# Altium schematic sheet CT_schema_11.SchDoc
size 387 x 385 mm
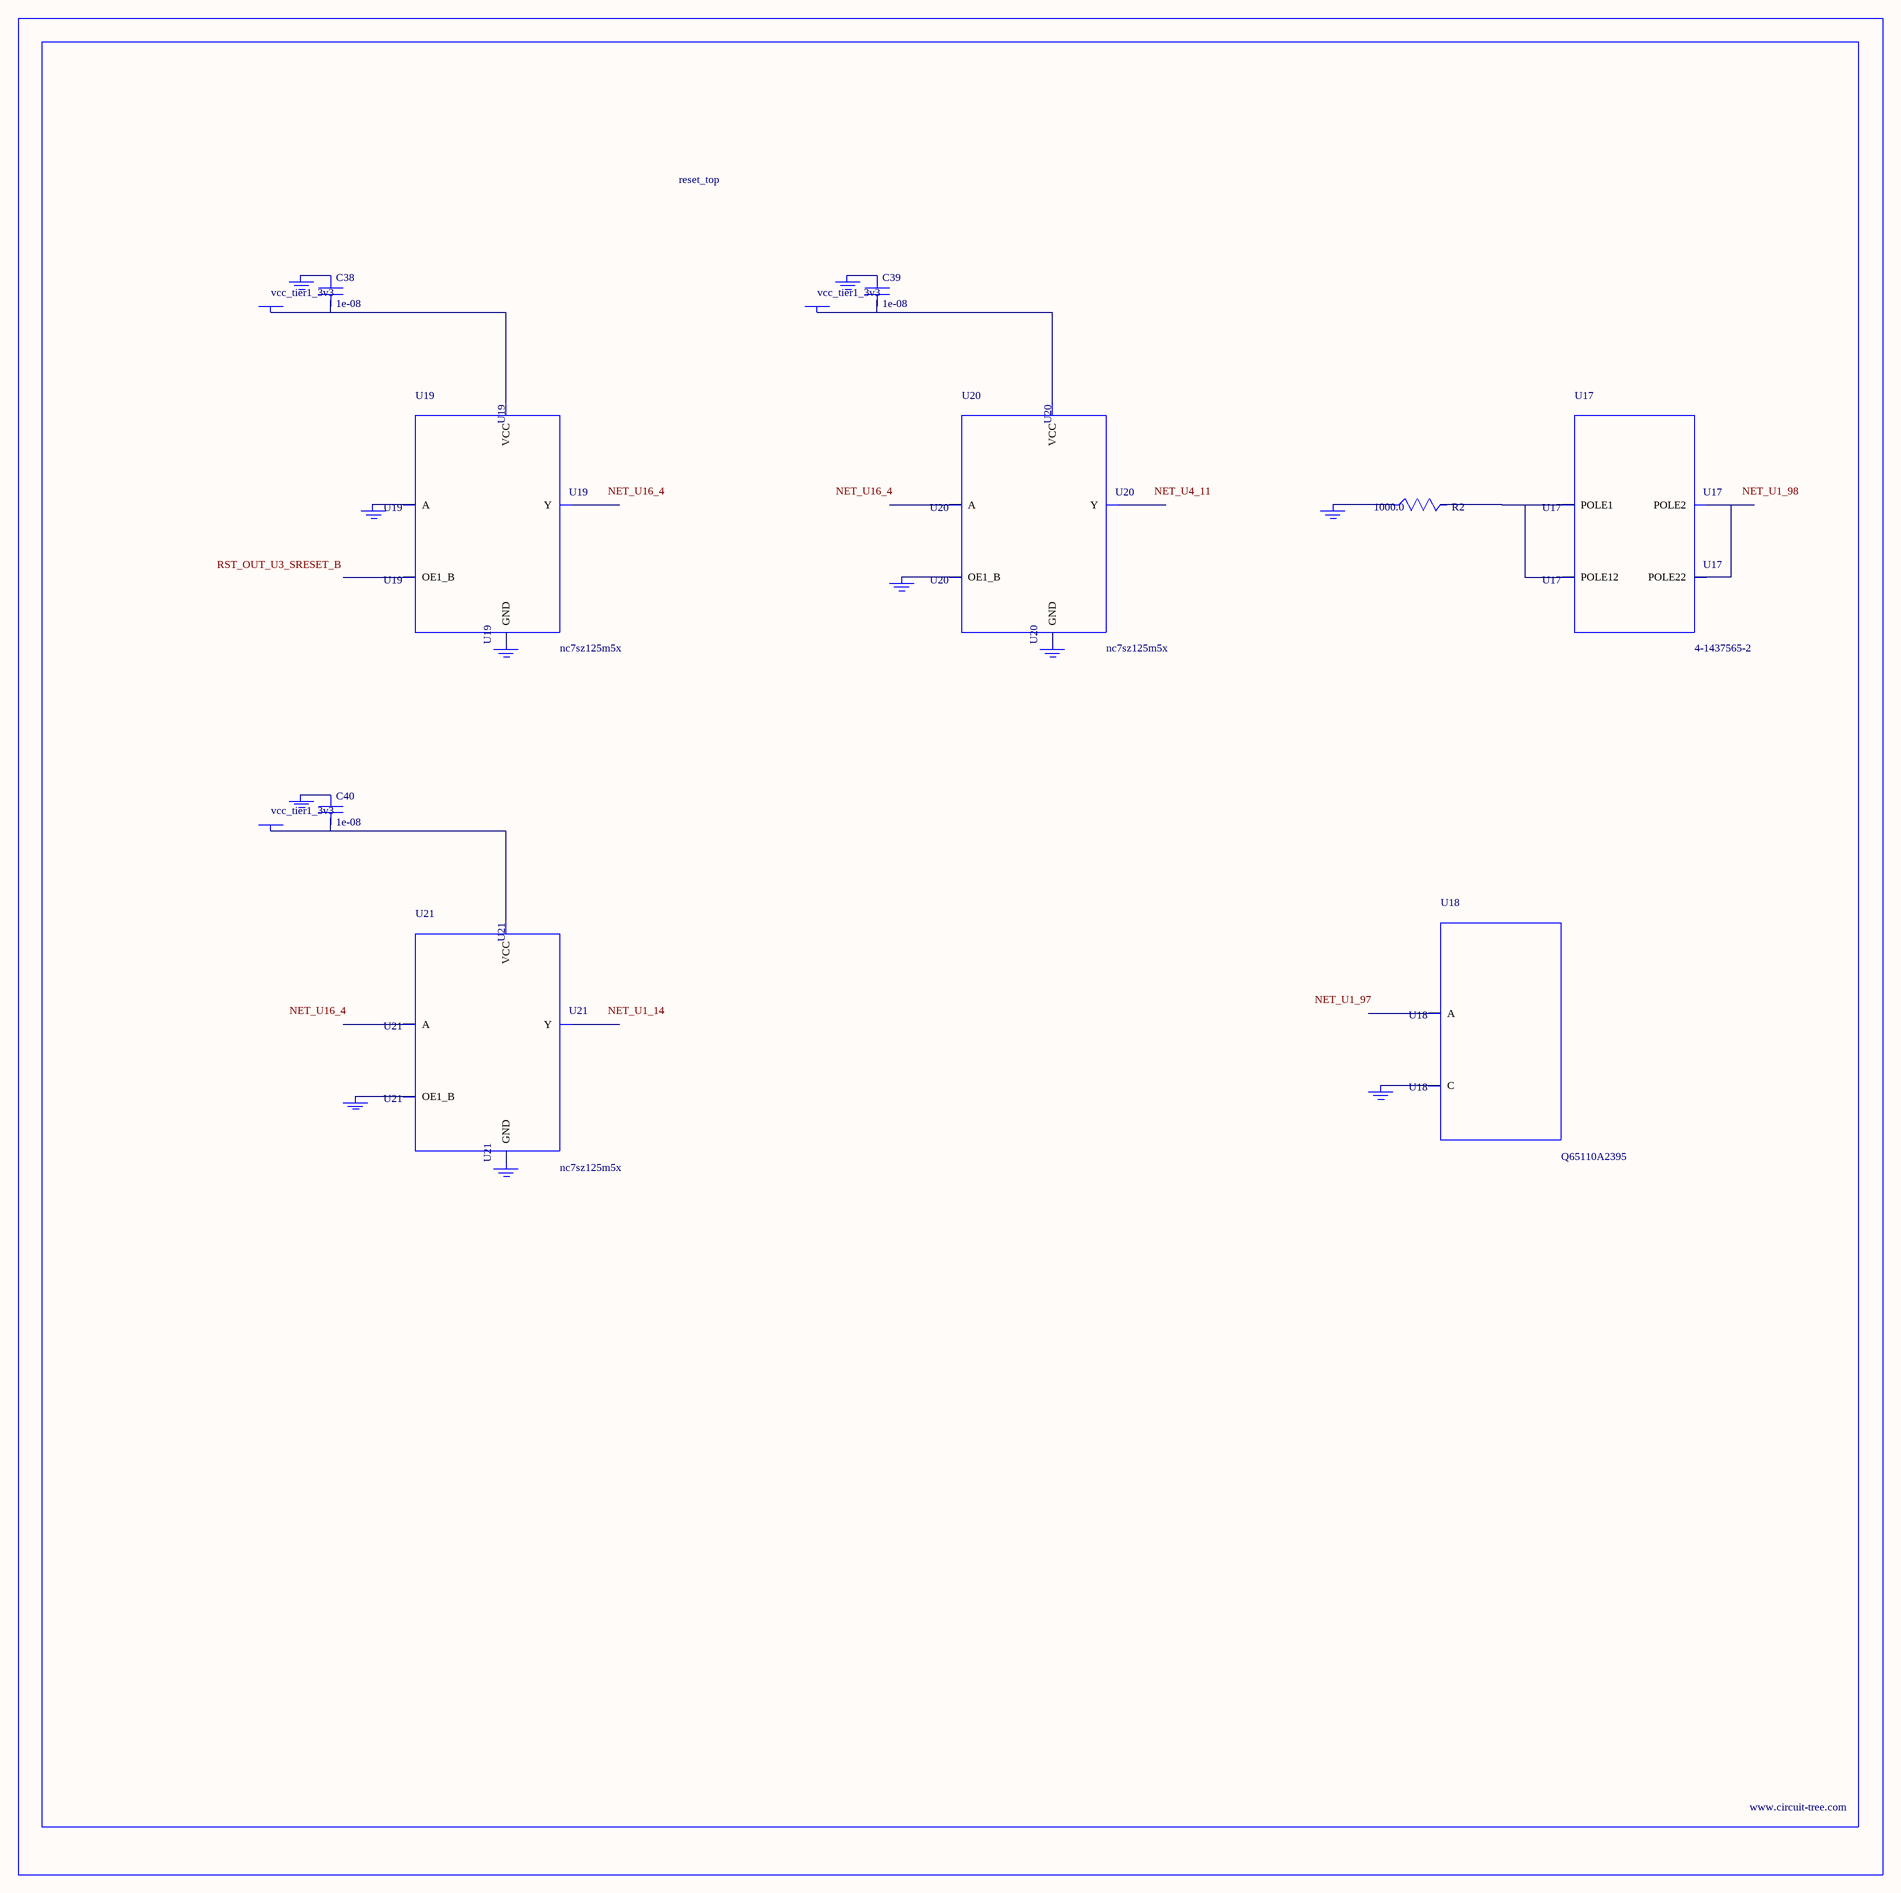
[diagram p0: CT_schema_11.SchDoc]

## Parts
BORDER10  (no value)
C38  1e-08  [C0402]
C39  1e-08  [C0402]
C40  1e-08  [C0402]
GND_INSTANCE_10_0  (no value)
GND_INSTANCE_10_1  (no value)
GND_INSTANCE_10_2  (no value)
GND_INSTANCE_10_3  (no value)
GND_INSTANCE_10_4  (no value)
GND_INSTANCE_10_5  (no value)
GND_INSTANCE_10_6  (no value)
GND_INSTANCE_10_7  (no value)
GND_INSTANCE_10_8  (no value)
GND_INSTANCE_10_9  (no value)
GND_INSTANCE_10_10  (no value)
POWER_INSTANCE_10_0  vcc_tier1_3v3
POWER_INSTANCE_10_1  vcc_tier1_3v3
POWER_INSTANCE_10_2  vcc_tier1_3v3
R2  1000.0  [R0603]
U17  4-1437565-2  [SW_4-1437565-2]
U18  Q65110A2395  [LGM67K-G1J2-24-Z]
U19  nc7sz125m5x  [NC7SZ125M5X]
U20  nc7sz125m5x  [NC7SZ125M5X]
U21  nc7sz125m5x  [NC7SZ125M5X]

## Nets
NetC38_1: C38.1 GND_INSTANCE_10_2.0(GND)
NetC38_2: C38.2 POWER_INSTANCE_10_0.0(PWR) U19.5(VCC)
NetC39_1: C39.1 GND_INSTANCE_10_5.0(GND)
NetC39_2: C39.2 POWER_INSTANCE_10_1.0(PWR) U20.5(VCC)
NetC40_1: C40.1 GND_INSTANCE_10_8.0(GND)
NetC40_2: C40.2 POWER_INSTANCE_10_2.0(PWR) U21.5(VCC)
NetGND_INSTANCE_10_0_0: GND_INSTANCE_10_0.0(GND) R2.1
NetGND_INSTANCE_10_1_0: GND_INSTANCE_10_1.0(GND) U18.C
NetGND_INSTANCE_10_3_0: GND_INSTANCE_10_3.0(GND) U19.2(A)
NetGND_INSTANCE_10_4_0: GND_INSTANCE_10_4.0(GND) U19.3(GND)
NetGND_INSTANCE_10_6_0: GND_INSTANCE_10_6.0(GND) U20.1(OE1_B)
NetGND_INSTANCE_10_7_0: GND_INSTANCE_10_7.0(GND) U20.3(GND)
NetGND_INSTANCE_10_9_0: GND_INSTANCE_10_9.0(GND) U21.1(OE1_B)
NetGND_INSTANCE_10_10_0: GND_INSTANCE_10_10.0(GND) U21.3(GND)
NetR2_2: R2.2 U17.1(POLE1) U17.2(POLE12)
NetU17_3: U17.3(POLE2) U17.4(POLE22)

Not connected (* = marked no-connect by the designer): U18 A; U19 1(OE1_B) 4(Y); U20 2(A) 4(Y); U21 2(A) 4(Y)

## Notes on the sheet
- Labels drawn without touching a wire or pin: NET_U1_14, NET_U1_97, NET_U1_98, NET_U4_11, NET_U16_4, RST_OUT_U3_SRESET_B

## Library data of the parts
BORDER10 = BORDER_PAGE10
C38-C40 = C0402C103K3RAC
GND_INSTANCE_10_0-GND_INSTANCE_10_10 = GND
POWER_INSTANCE_10_0-POWER_INSTANCE_10_2 = PWR
R2 = RC0603JR-071KL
